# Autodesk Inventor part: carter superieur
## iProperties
Author: chr
Shininess: 20.0
Angle Display Precision: 2
Document Length Units: 11269
Document Angle Units: 11283
Document Time Units: 11279
Document Mass Units: 11290
Document Length Units Precision: 3
Document Angle Units Precision: 2
Compacted: False
PropertySet Name: _Private Model Information
Created: 2002-03
Part Number: carter superieur
Material: Par défaut
Document SubType Name: Modélisation
Designer: chr
Control State: 0
Master: False
Checked Out: False
PropertySet Name: Design Tracking Control
Density: 0.0
Volumn: 0.0
Area: 0.0
PropertySet Name: Model Information
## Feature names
1. Extrusion1
2. Dépouille d'arête2
3. Dépouille d'arête3
4. Dépouille d'arête4
5. Perçage2 [Hole]
6. Perçage3 [Hole]
7. Extrusion2
8. Extrusion3
9. Perçage5 [Hole]
10. Coque2
11. Extrusion6
12. Extrusion9
13. Extrusion10
14. Extrusion11
